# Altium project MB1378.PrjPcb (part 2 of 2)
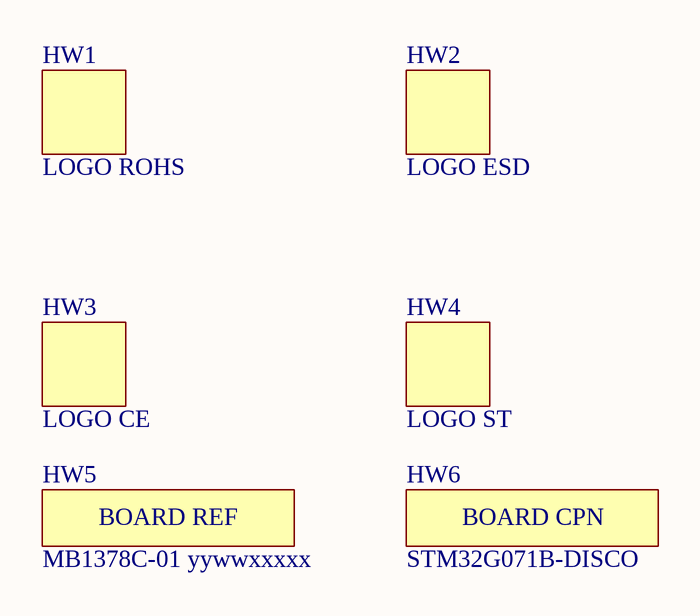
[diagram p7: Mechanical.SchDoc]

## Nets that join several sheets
3V3_LDO: USB_typeC_CurrentSensing (6 pins), MCU_Display (5 pins), Power_Supply (C3.1 C4.2 U1.4)
3V6_LDO: MCU_Display (C38.1 U9.5), Power_Supply (C7.2 U2.5)
5V: ST_LINK_V2_1 (D4.1 R51.2), MCU_Display (CN9.8), Power_Supply (10 pins)
5V_SMPS_VBUS: ST_LINK_V2_1 (D6.1), MCU_Display (CN1.2), Power_Supply (7 pins)
5V_STLK: ST_LINK_V2_1 (C33.2 U6.1), Power_Supply (D1.1 R1.2)
GND: USB_typeC_CurrentSensing (21 pins), ST_LINK_V2_1 (43 pins), MCU_Display (39 pins), Power_Supply (31 pins)
ALERT_CC1: USB_typeC_CurrentSensing (U11.3), MCU_Display (U8.38)
ALERT_CC2: USB_typeC_CurrentSensing (U12.3), MCU_Display (U8.39)
ALERT_VBUS: USB_typeC_CurrentSensing (U10.3), MCU_Display (U8.26)
DOOR_SENSE: USB_typeC_CurrentSensing (D3.2 SB16.2 SW1.2), MCU_Display (U8.48)
EN_SMPS: MCU_Display (U8.17), Power_Supply (Q3.1 R63.2)
ENCC1: USB_typeC_CurrentSensing (R58.2), MCU_Display (U8.30)
ENCC2: USB_typeC_CurrentSensing (R57.2), MCU_Display (U8.31)
I2C1_SCL: USB_typeC_CurrentSensing (R46.1 U10.5 U11.5 U12.5), MCU_Display (U8.60)
I2C1_SDA: USB_typeC_CurrentSensing (5 pins), MCU_Display (U8.61)
MCO: ST_LINK_V2_1 (C27.2 R18.2), MCU_Display (SB5.2)
NRST: ST_LINK_V2_1 (JP2.1), MCU_Display (B1.1 B1.3 C44.2 U8.12)
RD_CC1: USB_typeC_CurrentSensing (R62.1), MCU_Display (U8.32)
SMPS_ON: MCU_Display (U8.44), Power_Supply (R2.1 R5.2)
STLK_ON: MCU_Display (U8.43), Power_Supply (R1.1 R4.2)
STLK_SWCLK: ST_LINK_V2_1 (SB3.2), MCU_Display (R37.2 U8.46)
STLK_SWDIO: ST_LINK_V2_1 (SB2.2), MCU_Display (U8.45)
USBPD1_CC1: USB_typeC_CurrentSensing (SB8.2 T3.4 T3.7), MCU_Display (U8.36)
USBPD1_CC2: USB_typeC_CurrentSensing (SB7.2 T2.4 T2.7), MCU_Display (U8.35)
VBUS_P: USB_typeC_CurrentSensing (8 pins), Power_Supply (6 pins)
VCP_RX: ST_LINK_V2_1 (R22.2), MCU_Display (U8.1)
VCP_TX: ST_LINK_V2_1 (R23.1), MCU_Display (U8.64)

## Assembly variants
DEFAULT: not fitted C27 C42 C43 CN2 CN4 CN6 CN8 CN9 JP1 R13 R16 R41 R44 R53 R54 X3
